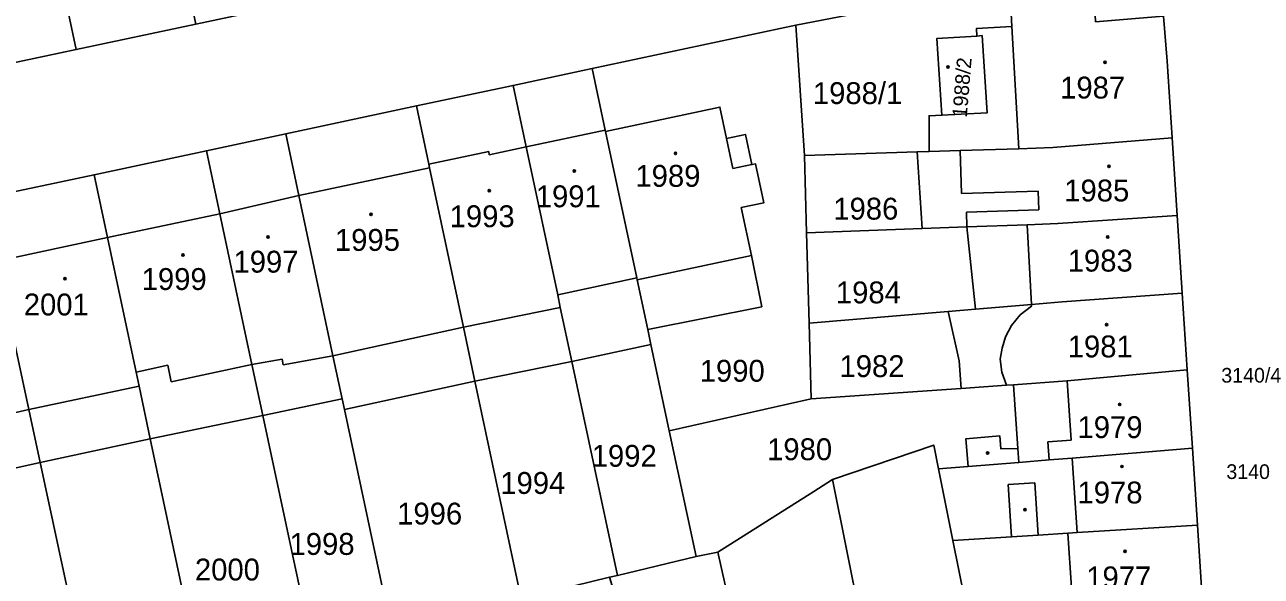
# Model space of a CAD drawing. Extents: x -596233 to -595156, y -1161235 to -1159375.
# Drawn here: x -595713.9 to -595617.7, y -1161019.3 to -1160976.5 of the extents above; entities that cross this region are included whole.
import ezdxf

# ---------------------------------------------------------------- set-up
doc = ezdxf.new("R2010")
doc.units = 0
for name, color, linetype in [('KN_CAR_KR', 7, 'Continuous'), ('KN_KULTURY', 7, 'Continuous'), ('KN_PARC_CIS_POZ', 7, 'Continuous'), ('KN_PARC_CIS_STAV', 7, 'Continuous'), ('KN_PARC_PLOCHA', 7, 'Continuous'), ('parcely_l', 7, 'Continuous')]:
    doc.layers.add(name, color=color, linetype=linetype)

msp = doc.modelspace()

# ---------------------------------------------------------------- linework, layer by layer
at = {"layer": 'KN_CAR_KR'}
for points in [[(-595637.13, -1160976.61), (-595636.59, -1160986.11)], [(-595674.91, -1160985.97), (-595668.76, -1160984.66)], [(-595677.78, -1160986.58), (-595674.91, -1160985.97)], [(-595659.33, -1160985.31), (-595658.83, -1160987.66)], [(-595682.49, -1160987.31), (-595677.83, -1160986.33)], [(-595677.83, -1160986.33), (-595677.78, -1160986.58)], [(-595641.16, -1160986.26), (-595641.06, -1160989.59)], [(-595682.43, -1160987.59), (-595692.59, -1160989.75)], [(-595658.83, -1160987.66), (-595657.36, -1160987.35)], [(-595698.74, -1160991.16), (-595692.59, -1160989.75)], [(-595641.06, -1160989.59), (-595635.09, -1160989.41)], [(-595635.09, -1160989.41), (-595635.05, -1160990.87)], [(-595707.48, -1160993.02), (-595698.74, -1160991.16)], [(-595635.05, -1160990.87), (-595640.66, -1160991.04)], [(-595640.66, -1160991.04), (-595640.63, -1160992.19)], [(-595635.62, -1160998.22), (-595635.96, -1160992.02)], [(-595716.07, -1160994.85), (-595707.48, -1160993.02)], [(-595666.28, -1160996.3), (-595657.39, -1160994.4)], [(-595672.46, -1160997.47), (-595666.32, -1160996.14)], [(-595679.79, -1160999.99), (-595672.26, -1160998.45)], [(-595635.62, -1160998.22), (-595635.62, -1160998.36), (-595636.49, -1160999.02), (-595637.17, -1160999.84), (-595637.64, -1161000.72), (-595637.89, -1161001.61), (-595638.06, -1161002.47), (-595637.93, -1161003.48), (-595637.55, -1161004.49)], [(-595689.94, -1161002.22), (-595679.79, -1160999.99)], [(-595693.81, -1161002.92), (-595689.94, -1161002.22)], [(-595705.25, -1161003.47), (-595702.78, -1161002.94)], [(-595702.78, -1161002.94), (-595702.51, -1161004.22)], [(-595702.51, -1161004.22), (-595696.24, -1161002.88)], [(-595696.24, -1161002.88), (-595693.89, -1161002.46)], [(-595693.89, -1161002.46), (-595693.81, -1161002.92)], [(-595632.83, -1161004.16), (-595632.53, -1161008.77)], [(-595713.6, -1161006.38), (-595705.02, -1161004.56)], [(-595722.18, -1161008.35), (-595713.6, -1161006.38)], [(-595632.53, -1161008.77), (-595634.33, -1161008.89)], [(-595634.33, -1161008.89), (-595634.24, -1161010.3)], [(-595636.59, -1161010.49), (-595636.68, -1161009.41)], [(-595632.44, -1161010.15), (-595632.06, -1161015.95)], [(-595637.43, -1161012.22), (-595635.35, -1161012.08)], [(-595637.17, -1161016.28), (-595637.43, -1161012.22)], [(-595635.35, -1161012.08), (-595635.09, -1161016.14)], [(-595632.78, -1161016), (-595632.49, -1161020.24)]]:
    msp.add_lwpolyline(points, dxfattribs=at)
at = {"layer": 'KN_KULTURY'}
for centre, radius in [((-595642.11, -1160979.76), 0.09), ((-595642.11, -1160979.76), 0.0398), ((-595629.89, -1160979.39), 0.09), ((-595629.89, -1160979.39), 0.0398), ((-595663.3, -1160986.47), 0.09), ((-595663.3, -1160986.47), 0.0398), ((-595671.17, -1160987.85), 0.09), ((-595671.17, -1160987.85), 0.0398), ((-595629.59, -1160987.49), 0.09), ((-595629.59, -1160987.49), 0.0398), ((-595677.79, -1160989.36), 0.09), ((-595677.79, -1160989.36), 0.0398), ((-595686.97, -1160991.22), 0.09), ((-595686.97, -1160991.22), 0.0398), ((-595694.99, -1160992.97), 0.09), ((-595694.99, -1160992.97), 0.0398), ((-595629.68, -1160992.97), 0.09), ((-595629.68, -1160992.97), 0.0398), ((-595701.61, -1160994.36), 0.09), ((-595701.61, -1160994.36), 0.0398), ((-595710.79, -1160996.22), 0.09), ((-595710.79, -1160996.22), 0.0398), ((-595629.77, -1160999.78), 0.09), ((-595629.77, -1160999.78), 0.0398), ((-595628.75, -1161005.99), 0.09), ((-595628.75, -1161005.99), 0.0398), ((-595639.03, -1161009.77), 0.09), ((-595639.03, -1161009.77), 0.0398), ((-595628.58, -1161010.81), 0.09), ((-595628.58, -1161010.81), 0.0398), ((-595636.12, -1161014.17), 0.09), ((-595636.12, -1161014.17), 0.0398), ((-595628.33, -1161017.41), 0.09), ((-595628.33, -1161017.41), 0.0398)]:
    msp.add_circle(centre, radius, dxfattribs=at)
at = {"layer": 'KN_PARC_PLOCHA'}
for points in [[(-595700.61, -1160976.44), (-595709.92, -1160978.4), (-595710.95, -1160973.5), (-595713.14, -1160963.07), (-595713.6, -1160960.45), (-595704.43, -1160958.32), (-595704, -1160960.37), (-595703.84, -1160961.13), (-595701.64, -1160971.55)], [(-595709.92, -1160978.4), (-595712.36, -1160978.92), (-595719.22, -1160980.36), (-595720.25, -1160975.47), (-595722.44, -1160965.01), (-595722.77, -1160963.53), (-595722.99, -1160962.46), (-595713.6, -1160960.45), (-595713.14, -1160963.07), (-595710.95, -1160973.5)], [(-595625.66, -1160973.1), (-595625.36, -1160975.82), (-595630.63, -1160976.24), (-595630.7, -1160975.18), (-595637.19, -1160975.6), (-595637.13, -1160976.61), (-595639.9, -1160976.77), (-595639.87, -1160977.35), (-595642.97, -1160977.54), (-595642.58, -1160983.51), (-595643.58, -1160983.55), (-595643.58, -1160985.53), (-595643.58, -1160986.33), (-595644.5, -1160986.36), (-595653.28, -1160986.65), (-595653.95, -1160976.51), (-595627.79, -1160971.45)], [(-595625.36, -1160975.82), (-595625.07, -1160979.3), (-595624.68, -1160985.27), (-595633.95, -1160986.02), (-595636.59, -1160986.11), (-595641.16, -1160986.26), (-595643.58, -1160986.33), (-595643.58, -1160985.53), (-595643.58, -1160983.55), (-595642.58, -1160983.51), (-595639.05, -1160983.31), (-595639.46, -1160977.32), (-595639.87, -1160977.35), (-595639.9, -1160976.77), (-595637.13, -1160976.61), (-595637.19, -1160975.6), (-595630.7, -1160975.18), (-595630.63, -1160976.24)], [(-595653.28, -1160986.65), (-595653.11, -1160992.65), (-595652.91, -1160999.66), (-595652.74, -1161005.55), (-595663.78, -1161008.04), (-595665.21, -1161001.33), (-595665.46, -1161000.16), (-595656.59, -1160998.39), (-595657.39, -1160994.4), (-595658.18, -1160990.69), (-595656.42, -1160990.31), (-595657.07, -1160987.29), (-595657.36, -1160987.35), (-595657.86, -1160985), (-595659.33, -1160985.31), (-595659.85, -1160982.87), (-595668.74, -1160984.77), (-595668.76, -1160984.66), (-595669.78, -1160979.88), (-595653.95, -1160976.51)], [(-595642.58, -1160983.51), (-595642.97, -1160977.54), (-595639.87, -1160977.35), (-595639.46, -1160977.32), (-595639.05, -1160983.31)], [(-595668.74, -1160984.77), (-595666.32, -1160996.14), (-595666.28, -1160996.3), (-595665.46, -1161000.16), (-595665.21, -1161001.33), (-595671.36, -1161002.66), (-595672.26, -1160998.45), (-595672.46, -1160997.47), (-595674.91, -1160985.97), (-595675.93, -1160981.19), (-595669.78, -1160979.88), (-595668.76, -1160984.66)], [(-595671.36, -1161002.66), (-595678.9, -1161004.19), (-595679.79, -1160999.99), (-595682.43, -1160987.59), (-595682.49, -1160987.31), (-595683.45, -1160982.79), (-595675.93, -1160981.19), (-595674.91, -1160985.97), (-595672.46, -1160997.47), (-595672.26, -1160998.45)], [(-595678.9, -1161004.19), (-595689.05, -1161006.38), (-595689.23, -1161005.55), (-595689.94, -1161002.22), (-595692.59, -1160989.75), (-595693.61, -1160984.96), (-595683.45, -1160982.79), (-595682.49, -1160987.31), (-595682.43, -1160987.59), (-595679.79, -1160999.99)], [(-595665.46, -1161000.16), (-595666.28, -1160996.3), (-595666.32, -1160996.14), (-595668.74, -1160984.77), (-595659.85, -1160982.87), (-595659.33, -1160985.31), (-595657.86, -1160985), (-595657.36, -1160987.35), (-595657.07, -1160987.29), (-595656.42, -1160990.31), (-595658.18, -1160990.69), (-595657.39, -1160994.4), (-595656.59, -1160998.39)], [(-595689.23, -1161005.55), (-595695.4, -1161006.84), (-595696.24, -1161002.88), (-595698.74, -1160991.16), (-595699.78, -1160986.27), (-595693.61, -1160984.96), (-595692.59, -1160989.75), (-595689.94, -1161002.22)], [(-595624.29, -1160991.31), (-595633.57, -1160991.93), (-595635.96, -1160992.02), (-595640.63, -1160992.19), (-595644.11, -1160992.32), (-595644.5, -1160986.36), (-595643.58, -1160986.33), (-595641.16, -1160986.26), (-595636.59, -1160986.11), (-595633.95, -1160986.02), (-595624.68, -1160985.27)], [(-595695.4, -1161006.84), (-595704.15, -1161008.67), (-595705.02, -1161004.56), (-595705.25, -1161003.47), (-595707.48, -1160993.02), (-595708.52, -1160988.13), (-595699.78, -1160986.27), (-595698.74, -1160991.16), (-595696.24, -1161002.88)], [(-595644.11, -1160992.32), (-595653.11, -1160992.65), (-595653.28, -1160986.65), (-595644.5, -1160986.36)], [(-595704.15, -1161008.67), (-595712.71, -1161010.49), (-595713.6, -1161006.38), (-595716.07, -1160994.85), (-595717.12, -1160989.96), (-595708.52, -1160988.13), (-595707.48, -1160993.02), (-595705.25, -1161003.47), (-595705.02, -1161004.56)], [(-595712.71, -1161010.49), (-595721.32, -1161012.41), (-595722.18, -1161008.35), (-595724.67, -1160996.68), (-595725.71, -1160991.79), (-595717.12, -1160989.96), (-595716.07, -1160994.85), (-595713.6, -1161006.38)], [(-595623.89, -1160997.33), (-595633.23, -1160998.02), (-595635.62, -1160998.22), (-595639.97, -1160998.58), (-595640.63, -1160992.19), (-595635.96, -1160992.02), (-595633.57, -1160991.93), (-595624.29, -1160991.31)], [(-595639.97, -1160998.58), (-595642.09, -1160998.76), (-595652.91, -1160999.66), (-595653.11, -1160992.65), (-595644.11, -1160992.32), (-595640.63, -1160992.19)], [(-595623.5, -1161003.3), (-595632.83, -1161004.16), (-595637.01, -1161004.45), (-595637.55, -1161004.49), (-595641.08, -1161004.74), (-595641.23, -1161002.6), (-595642.09, -1160998.76), (-595639.97, -1160998.58), (-595635.62, -1160998.22), (-595633.23, -1160998.02), (-595623.89, -1160997.33)], [(-595641.08, -1161004.74), (-595652.74, -1161005.55), (-595652.91, -1160999.66), (-595642.09, -1160998.76), (-595641.23, -1161002.6)], [(-595663.78, -1161008.04), (-595661.7, -1161017.8), (-595667.82, -1161019.28), (-595671.36, -1161002.66), (-595665.21, -1161001.33)], [(-595667.82, -1161019.28), (-595668.42, -1161019.4), (-595675.3, -1161021.09), (-595678.9, -1161004.19), (-595671.36, -1161002.66)], [(-595675.3, -1161021.09), (-595676.85, -1161021.56), (-595679.66, -1161022.52), (-595685.24, -1161024.28), (-595689.05, -1161006.38), (-595678.9, -1161004.19)], [(-595623.1, -1161009.39), (-595632.44, -1161010.15), (-595634.24, -1161010.3), (-595636.59, -1161010.49), (-595640.54, -1161010.8), (-595640.72, -1161008.65), (-595638.08, -1161008.43), (-595638, -1161009.43), (-595636.68, -1161009.41), (-595637.01, -1161004.45), (-595632.83, -1161004.16), (-595623.5, -1161003.3)], [(-595640.54, -1161010.8), (-595642.85, -1161010.99), (-595643.22, -1161009.14), (-595651.1, -1161011.83), (-595652.54, -1161012.74), (-595660.01, -1161017.46), (-595661.7, -1161017.8), (-595663.78, -1161008.04), (-595652.74, -1161005.55), (-595641.08, -1161004.74), (-595637.55, -1161004.49), (-595637.01, -1161004.45), (-595636.68, -1161009.41), (-595638, -1161009.43), (-595638.08, -1161008.43), (-595640.72, -1161008.65)], [(-595689.05, -1161006.38), (-595685.24, -1161024.28), (-595686.21, -1161024.68), (-595691.36, -1161025.79), (-595695.4, -1161006.84), (-595689.23, -1161005.55)], [(-595691.36, -1161025.79), (-595693.69, -1161026.42), (-595697.76, -1161028.4), (-595699.74, -1161029.36), (-595704.15, -1161008.67), (-595695.4, -1161006.84)], [(-595699.74, -1161029.36), (-595700.11, -1161029.66), (-595699.72, -1161030.73), (-595706.08, -1161033.06), (-595707.74, -1161033.67), (-595712.71, -1161010.49), (-595704.15, -1161008.67)], [(-595642.85, -1161010.99), (-595641.73, -1161016.57), (-595640.37, -1161023.34), (-595639.19, -1161029.22), (-595637.57, -1161037.26), (-595636.93, -1161040.34), (-595636.52, -1161042.66), (-595643.34, -1161043.68), (-595644.61, -1161044.04), (-595651.1, -1161011.83), (-595643.22, -1161009.14)], [(-595622.71, -1161015.36), (-595632.06, -1161015.95), (-595632.78, -1161016), (-595635.09, -1161016.14), (-595637.17, -1161016.28), (-595641.73, -1161016.57), (-595642.85, -1161010.99), (-595640.54, -1161010.8), (-595636.59, -1161010.49), (-595634.24, -1161010.3), (-595632.44, -1161010.15), (-595623.1, -1161009.39)], [(-595707.74, -1161033.67), (-595712.21, -1161035.31), (-595716.2, -1161036.45), (-595721.32, -1161012.41), (-595712.71, -1161010.49)], [(-595644.61, -1161044.04), (-595652.28, -1161046.05), (-595653.29, -1161046.35), (-595653.75, -1161045.27), (-595660.01, -1161017.46), (-595652.54, -1161012.74), (-595651.1, -1161011.83)], [(-595622.26, -1161022.21), (-595631.54, -1161022.79), (-595632.63, -1161022.85), (-595635.55, -1161023.04), (-595640.37, -1161023.34), (-595641.73, -1161016.57), (-595637.17, -1161016.28), (-595635.09, -1161016.14), (-595632.78, -1161016), (-595632.06, -1161015.95), (-595622.71, -1161015.36)], [(-595653.75, -1161045.27), (-595656.32, -1161046.07), (-595655.84, -1161047.59), (-595656.97, -1161047.98), (-595658.34, -1161043.3), (-595660.85, -1161044.03), (-595662.03, -1161040.21), (-595663.09, -1161036.75), (-595668.42, -1161019.4), (-595667.82, -1161019.28), (-595661.7, -1161017.8), (-595660.01, -1161017.46)]]:
    msp.add_lwpolyline(points, close=True, dxfattribs=at)
for points in [[(-595719.22, -1160980.36), (-595712.36, -1160978.92), (-595709.92, -1160978.4), (-595700.61, -1160976.44), (-595693.75, -1160974.99), (-595687.28, -1160973.63), (-595681.01, -1160972.31), (-595674.65, -1160970.96), (-595665.07, -1160968.95), (-595653.76, -1160966.55), (-595628.48, -1160961.18), (-595626.26, -1160959.92), (-595625.66, -1160973.1), (-595627.79, -1160971.45), (-595653.95, -1160976.51), (-595669.78, -1160979.88), (-595675.93, -1160981.19), (-595683.45, -1160982.79), (-595693.61, -1160984.96), (-595699.78, -1160986.27), (-595708.52, -1160988.13), (-595717.12, -1160989.96)], [(-595622.26, -1161022.21), (-595622.71, -1161015.36), (-595623.1, -1161009.39), (-595623.5, -1161003.3), (-595623.89, -1160997.33), (-595624.29, -1160991.31), (-595624.68, -1160985.27), (-595625.07, -1160979.3), (-595625.36, -1160975.82)]]:
    msp.add_lwpolyline(points, dxfattribs=at)
at = {"layer": 'parcely_l'}
for points in [[(-595709.92, -1160978.4), (-595710.95, -1160973.5), (-595713.14, -1160963.07), (-595713.6, -1160960.45)], [(-595653.95, -1160976.51), (-595627.79, -1160971.45), (-595625.66, -1160973.1)], [(-595639.87, -1160977.35), (-595639.9, -1160976.77), (-595637.13, -1160976.61), (-595637.19, -1160975.6), (-595630.7, -1160975.18), (-595630.63, -1160976.24), (-595625.36, -1160975.82)], [(-595625.36, -1160975.82), (-595625.07, -1160979.3), (-595624.68, -1160985.27)], [(-595700.61, -1160976.44), (-595709.92, -1160978.4)], [(-595669.78, -1160979.88), (-595653.95, -1160976.51)], [(-595653.95, -1160976.51), (-595653.28, -1160986.65)], [(-595642.58, -1160983.51), (-595639.05, -1160983.31), (-595639.46, -1160977.32), (-595639.87, -1160977.35)], [(-595642.58, -1160983.51), (-595642.97, -1160977.54), (-595639.87, -1160977.35)], [(-595709.92, -1160978.4), (-595712.36, -1160978.92), (-595719.22, -1160980.36)], [(-595675.93, -1160981.19), (-595669.78, -1160979.88)], [(-595668.74, -1160984.77), (-595668.76, -1160984.66), (-595669.78, -1160979.88)], [(-595683.45, -1160982.79), (-595675.93, -1160981.19)], [(-595671.36, -1161002.66), (-595672.26, -1160998.45), (-595672.46, -1160997.47), (-595674.91, -1160985.97), (-595675.93, -1160981.19)], [(-595693.61, -1160984.96), (-595683.45, -1160982.79)], [(-595683.45, -1160982.79), (-595682.49, -1160987.31), (-595682.43, -1160987.59), (-595679.79, -1160999.99), (-595678.9, -1161004.19)], [(-595665.46, -1161000.16), (-595656.59, -1160998.39), (-595657.39, -1160994.4), (-595658.18, -1160990.69), (-595656.42, -1160990.31), (-595657.07, -1160987.29), (-595657.36, -1160987.35), (-595657.86, -1160985), (-595659.33, -1160985.31), (-595659.85, -1160982.87), (-595668.74, -1160984.77)], [(-595643.58, -1160986.33), (-595643.58, -1160985.53), (-595643.58, -1160983.55), (-595642.58, -1160983.51)], [(-595699.78, -1160986.27), (-595693.61, -1160984.96)], [(-595689.23, -1161005.55), (-595689.94, -1161002.22), (-595692.59, -1160989.75), (-595693.61, -1160984.96)], [(-595665.46, -1161000.16), (-595666.28, -1160996.3), (-595666.32, -1160996.14), (-595668.74, -1160984.77)], [(-595624.68, -1160985.27), (-595633.95, -1160986.02), (-595636.59, -1160986.11), (-595641.16, -1160986.26), (-595643.58, -1160986.33)], [(-595624.29, -1160991.31), (-595624.68, -1160985.27)], [(-595708.52, -1160988.13), (-595699.78, -1160986.27)], [(-595699.78, -1160986.27), (-595698.74, -1160991.16), (-595696.24, -1161002.88), (-595695.4, -1161006.84)], [(-595653.28, -1160986.65), (-595644.5, -1160986.36)], [(-595653.28, -1160986.65), (-595653.11, -1160992.65)], [(-595643.58, -1160986.33), (-595644.5, -1160986.36)], [(-595644.5, -1160986.36), (-595644.11, -1160992.32)], [(-595717.12, -1160989.96), (-595708.52, -1160988.13)], [(-595708.52, -1160988.13), (-595707.48, -1160993.02), (-595705.25, -1161003.47), (-595705.02, -1161004.56), (-595704.15, -1161008.67)], [(-595712.71, -1161010.49), (-595713.6, -1161006.38), (-595716.07, -1160994.85), (-595717.12, -1160989.96)], [(-595640.63, -1160992.19), (-595635.96, -1160992.02), (-595633.57, -1160991.93), (-595624.29, -1160991.31)], [(-595624.29, -1160991.31), (-595623.89, -1160997.33)], [(-595644.11, -1160992.32), (-595653.11, -1160992.65)], [(-595653.11, -1160992.65), (-595652.91, -1160999.66)], [(-595644.11, -1160992.32), (-595640.63, -1160992.19)], [(-595639.97, -1160998.58), (-595640.63, -1160992.19)], [(-595623.89, -1160997.33), (-595633.23, -1160998.02), (-595635.62, -1160998.22), (-595639.97, -1160998.58)], [(-595623.5, -1161003.3), (-595623.89, -1160997.33)], [(-595652.91, -1160999.66), (-595642.09, -1160998.76)], [(-595642.09, -1160998.76), (-595639.97, -1160998.58)], [(-595642.09, -1160998.76), (-595641.23, -1161002.6), (-595641.08, -1161004.74)], [(-595665.21, -1161001.33), (-595665.46, -1161000.16)], [(-595652.91, -1160999.66), (-595652.74, -1161005.55)], [(-595671.36, -1161002.66), (-595665.21, -1161001.33)], [(-595663.78, -1161008.04), (-595665.21, -1161001.33)], [(-595678.9, -1161004.19), (-595671.36, -1161002.66)], [(-595667.82, -1161019.28), (-595671.36, -1161002.66)], [(-595678.9, -1161004.19), (-595689.05, -1161006.38)], [(-595678.9, -1161004.19), (-595675.3, -1161021.09)], [(-595637.01, -1161004.45), (-595632.83, -1161004.16), (-595623.5, -1161003.3)], [(-595623.5, -1161003.3), (-595623.1, -1161009.39)], [(-595652.74, -1161005.55), (-595641.08, -1161004.74)], [(-595641.08, -1161004.74), (-595637.55, -1161004.49), (-595637.01, -1161004.45)], [(-595637.01, -1161004.45), (-595636.68, -1161009.41), (-595638, -1161009.43), (-595638.08, -1161008.43), (-595640.72, -1161008.65), (-595640.54, -1161010.8)], [(-595695.4, -1161006.84), (-595689.23, -1161005.55)], [(-595689.23, -1161005.55), (-595689.05, -1161006.38)], [(-595652.74, -1161005.55), (-595663.78, -1161008.04)], [(-595704.15, -1161008.67), (-595695.4, -1161006.84)], [(-595695.4, -1161006.84), (-595691.36, -1161025.79)], [(-595689.05, -1161006.38), (-595685.24, -1161024.28)], [(-595661.7, -1161017.8), (-595663.78, -1161008.04)], [(-595712.71, -1161010.49), (-595704.15, -1161008.67)], [(-595704.15, -1161008.67), (-595699.74, -1161029.36)], [(-595642.85, -1161010.99), (-595643.22, -1161009.14), (-595651.1, -1161011.83)], [(-595640.54, -1161010.8), (-595636.59, -1161010.49), (-595634.24, -1161010.3), (-595632.44, -1161010.15), (-595623.1, -1161009.39)], [(-595623.1, -1161009.39), (-595622.71, -1161015.36)], [(-595721.32, -1161012.41), (-595712.71, -1161010.49)], [(-595707.74, -1161033.67), (-595712.71, -1161010.49)], [(-595642.85, -1161010.99), (-595640.54, -1161010.8)], [(-595651.1, -1161011.83), (-595652.54, -1161012.74), (-595660.01, -1161017.46)], [(-595644.61, -1161044.04), (-595651.1, -1161011.83)], [(-595641.73, -1161016.57), (-595642.85, -1161010.99)], [(-595622.71, -1161015.36), (-595632.06, -1161015.95), (-595632.78, -1161016), (-595635.09, -1161016.14), (-595637.17, -1161016.28), (-595641.73, -1161016.57)], [(-595622.71, -1161015.36), (-595622.26, -1161022.21)], [(-595641.73, -1161016.57), (-595640.37, -1161023.34)], [(-595660.01, -1161017.46), (-595661.7, -1161017.8)], [(-595653.75, -1161045.27), (-595660.01, -1161017.46)], [(-595667.82, -1161019.28), (-595661.7, -1161017.8)], [(-595668.42, -1161019.4), (-595667.82, -1161019.28)]]:
    msp.add_lwpolyline(points, dxfattribs=at)

# ---------------------------------------------------------------- texts
at = {"layer": 'KN_PARC_CIS_POZ'}
for s, height, p in [('1988/1', 1.7, (-595652.6166, -1160982.64)), ('1986', 1.7, (-595651.0266, -1160991.62)), ('1984', 1.7, (-595650.8266, -1160998.13)), ('1982', 1.7, (-595650.5466, -1161003.86)), ('1990', 1.7, (-595661.4166, -1161004.22)), ('3140/4', 1.14, (-595620.8505, -1161004.2893)), ('1980', 1.7, (-595656.1766, -1161010.32)), ('1992', 1.7, (-595669.8166, -1161010.83)), ('3140/3', 1.14, (-595620.46, -1161011.78)), ('1994', 1.7, (-595676.9266, -1161012.94)), ('1996', 1.7, (-595684.9466, -1161015.32)), ('1998', 1.7, (-595693.3166, -1161017.68)), ('2000', 1.7, (-595700.6766, -1161019.67))]:
    msp.add_text(s, height=height, dxfattribs=at).set_placement(p)
at = {"layer": 'KN_PARC_CIS_STAV'}
msp.add_text('1988/2', height=1.14, rotation=85.192474, dxfattribs=at).set_placement((-595640.6507, -1160983.7186))
for s, p in [('1987', (-595633.3866, -1160982.21)), ('1989', (-595666.4166, -1160989.07)), ('1985', (-595633.0666, -1160990.21)), ('1991', (-595674.1666, -1160990.66)), ('1993', (-595680.8666, -1160992.21)), ('1995', (-595689.7866, -1160994.05)), ('1997', (-595697.6766, -1160995.74)), ('1983', (-595632.7966, -1160995.66)), ('1999', (-595704.8166, -1160997.09)), ('2001', (-595713.9866, -1160999.07)), ('1981', (-595632.7966, -1161002.33)), ('1979', (-595632.0366, -1161008.6)), ('1978', (-595632.0366, -1161013.68)), ('1977', (-595631.3566, -1161020.28))]:
    msp.add_text(s, height=1.7, dxfattribs=at).set_placement(p)

doc.saveas('drawing.dxf')
